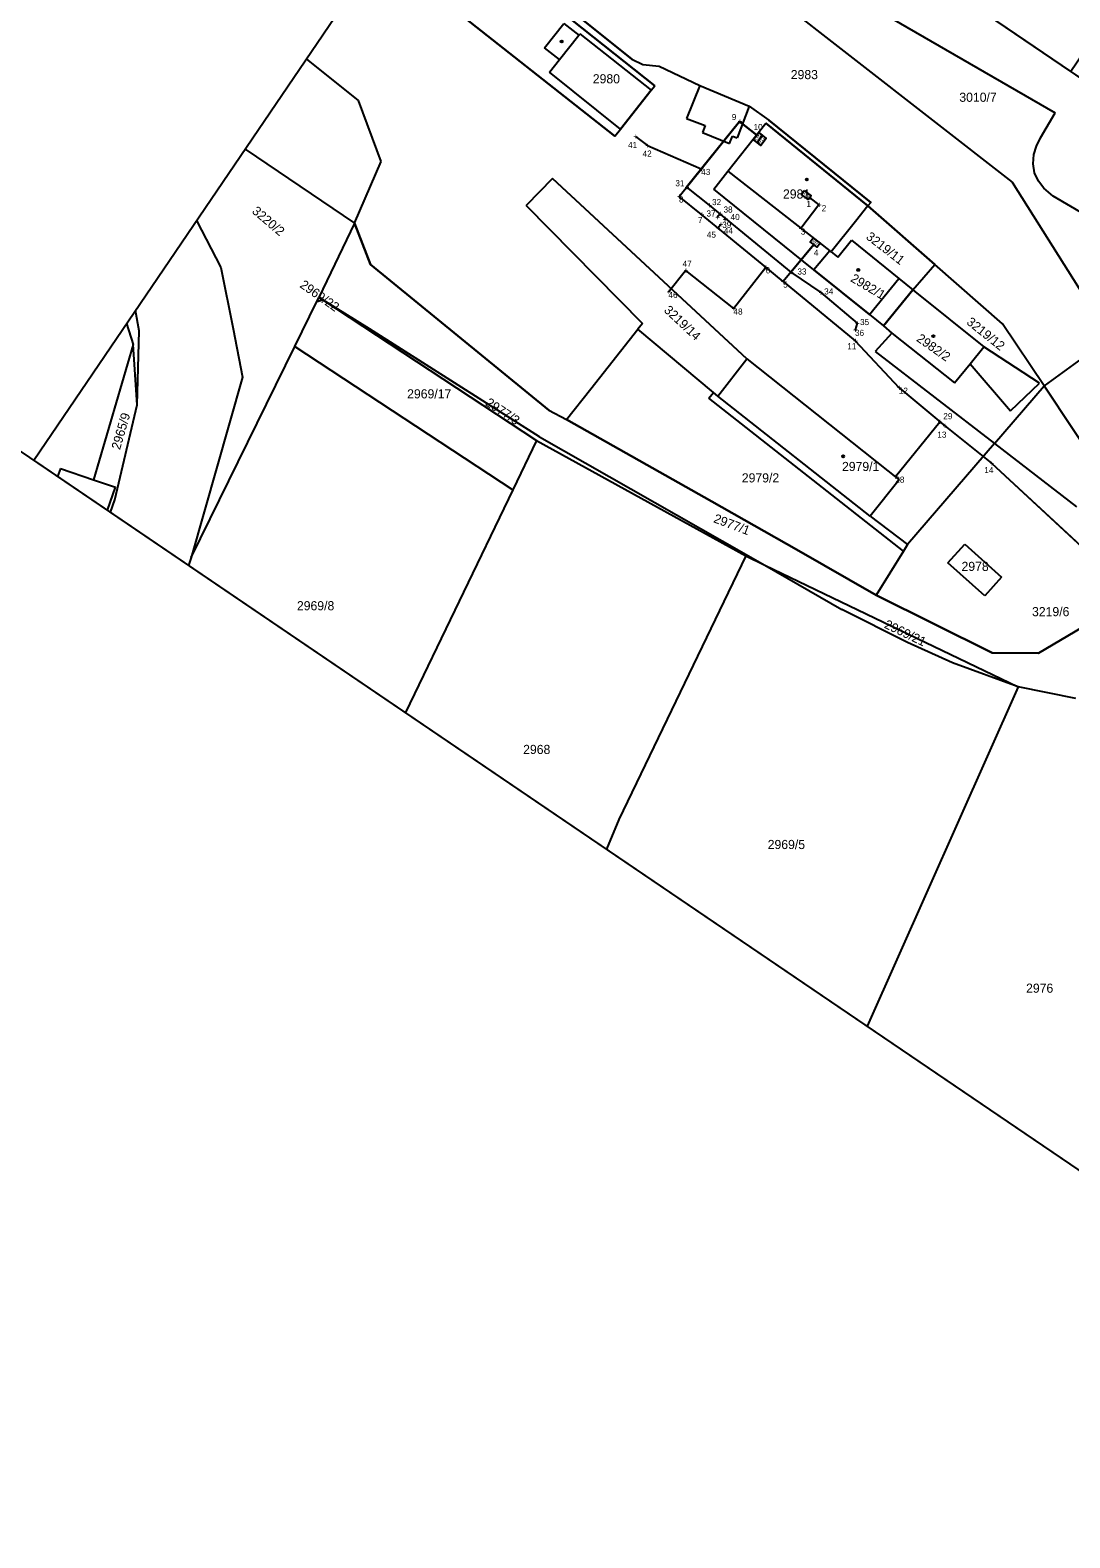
# Model space of a CAD drawing. Extents: x -620450 to -619936, y -1122925 to -1122443.
# Drawn here: x -620363.8 to -620193.1, y -1122924.7 to -1122677.1 of the extents above; entities that cross this region are included whole.
import ezdxf

# ---------------------------------------------------------------- set-up
doc = ezdxf.new("R2010")
doc.units = 0
for name, color, linetype in [('060603_ROZVODY_NN', 7, 'Continuous'), ('BODY', 7, 'Continuous'), ('BODY POPIS', 7, 'Continuous'), ('RÁMY', 7, 'Continuous'), ('UZEMNĚNÍ', 7, 'Continuous'), ('Vrstva 53', 7, 'Continuous'), ('Vrstva 55', 7, 'Continuous'), ('Vrstva 56', 7, 'Continuous'), ('Vrstva 57', 7, 'Continuous')]:
    doc.layers.add(name, color=color, linetype=linetype)

msp = doc.modelspace()

# ---------------------------------------------------------------- linework, layer by layer
at = {"layer": '060603_ROZVODY_NN'}
msp.add_line((-620250.43, -1122708.95), (-620250.9, -1122709.52), dxfattribs=at)
for points in [[(-620235.16, -1122712.24), (-620240.17, -1122718.34), (-620243.03, -1122716), (-620253.57, -1122707.33), (-620257.27, -1122704.36), (-620247.33, -1122692.03), (-620244.52, -1122694.3)], [(-620235.81, -1122704.58), (-620234.3, -1122705.74), (-620237.27, -1122709.63)], [(-620259, -1122720.03), (-620256.2, -1122716.51), (-620248.32, -1122722.77), (-620243.03, -1122716)], [(-620240.17, -1122718.34), (-620228.34, -1122728.07), (-620221.17, -1122735.76), (-620213.63, -1122742.04), (-620205.95, -1122748.19), (-620177.51, -1122774.52), (-620185.52, -1122781.05), (-620181.59, -1122785.57), (-620173.13, -1122796.4), (-620158.91, -1122820.61), (-620151.64, -1122838.53), (-620148.85, -1122845.74), (-620146.97, -1122851.79), (-620142.65, -1122873.56), (-620132.31, -1122871.72), (-620130.54, -1122883.68), (-620130.19, -1122888.41), (-620130.04, -1122888.39)]]:
    msp.add_lwpolyline(points, dxfattribs=at)
for points in [[(-620245.07, -1122694.99), (-620244.18, -1122693.87), (-620243.57, -1122694.36), (-620244.45, -1122695.48)], [(-620244.45, -1122695.48), (-620243.57, -1122694.36), (-620242.95, -1122694.85), (-620243.84, -1122695.97)], [(-620236.71, -1122703.4), (-620235.57, -1122704.27), (-620236.05, -1122704.89), (-620237.18, -1122704.03)], [(-620235.25, -1122711.18), (-620234.12, -1122712.05), (-620234.59, -1122712.68), (-620235.73, -1122711.81)]]:
    msp.add_lwpolyline(points, close=True, dxfattribs=at)
at = {"layer": 'RÁMY'}
for points in [[(-620196.37, -1122501.99), (-620109.51, -1122560.98), (-620192.94, -1122683.83), (-620279.8, -1122624.84)], [(-620366.66, -1122565.85), (-620019.21, -1122801.81), (-620102.64, -1122924.66), (-620450.09, -1122688.7)], [(-620279.8, -1122624.84), (-620019.21, -1122801.81), (-620102.64, -1122924.66), (-620363.23, -1122747.69)]]:
    msp.add_lwpolyline(points, close=True, dxfattribs=at)
at = {"layer": 'UZEMNĚNÍ'}
for p, q in [((-620250.99, -1122707.76), (-620250.55, -1122707.22)), ((-620249.79, -1122708.16), (-620249.64, -1122707.97))]:
    msp.add_line(p, q, dxfattribs=at)
for points in [[(-620244.52, -1122694.3), (-620247.33, -1122692.03), (-620256.03, -1122702.83), (-620252.31, -1122705.78), (-620238.9, -1122716.8), (-620235.16, -1122712.24)], [(-620264.43, -1122694.51), (-620262.46, -1122696.02), (-620253.62, -1122699.84)], [(-620238.9, -1122716.8), (-620233.99, -1122720.16), (-620228.02, -1122725.18), (-620228.37, -1122726.26)], [(-620221.75, -1122750.37), (-620214.46, -1122741.38), (-620205.95, -1122748.19), (-620176.84, -1122775.14)]]:
    msp.add_lwpolyline(points, dxfattribs=at)
at = {"layer": 'Vrstva 53'}
for p, q in [((-620299.15, -1122656.1), (-620261.22, -1122686.17)), ((-620298.73, -1122654.76), (-620265, -1122681.82)), ((-620267.81, -1122694.49), (-620302.66, -1122666.96)), ((-620309.9, -1122688.62), (-620318.44, -1122681.74)), ((-620265, -1122681.82), (-620263.22, -1122682.69)), ((-620263.22, -1122682.69), (-620260.55, -1122682.94)), ((-620260.55, -1122682.94), (-620253.83, -1122686.12)), ((-620261.82, -1122686.93), (-620261.22, -1122686.17)), ((-620253.83, -1122686.12), (-620245.73, -1122689.53)), ((-620306.2, -1122698.65), (-620309.9, -1122688.62)), ((-620261.82, -1122686.93), (-620266.86, -1122693.31)), ((-620245.73, -1122689.53), (-620242.51, -1122691.82)), ((-620267.81, -1122694.49), (-620266.86, -1122693.31)), ((-620249.26, -1122700.23), (-620243.01, -1122692.32)), ((-620226.24, -1122705.93), (-620243.01, -1122692.32)), ((-620310.57, -1122708.76), (-620306.2, -1122698.65)), ((-620251.53, -1122703.16), (-620249.26, -1122700.23)), ((-620278.07, -1122701.42), (-620282.38, -1122705.84)), ((-620278.07, -1122701.42), (-620246.12, -1122731.05)), ((-620235.14, -1122716.41), (-620251.53, -1122703.16)), ((-620263.28, -1122725.23), (-620282.38, -1122705.84)), ((-620226.24, -1122705.93), (-620228.28, -1122708.48)), ((-620226.24, -1122705.93), (-620215.29, -1122715.52)), ((-620228.28, -1122708.48), (-620232.27, -1122713.47)), ((-620307.94, -1122715.53), (-620310.57, -1122708.76)), ((-620232.51, -1122713.28), (-620235.14, -1122716.41)), ((-620232.27, -1122713.47), (-620232.51, -1122713.28)), ((-620232.27, -1122713.47), (-620231.2, -1122714.35)), ((-620231.2, -1122714.35), (-620228.95, -1122711.56)), ((-620228.95, -1122711.56), (-620221.19, -1122717.82)), ((-620278.65, -1122739.48), (-620307.94, -1122715.53)), ((-620218.86, -1122719.7), (-620215.29, -1122715.52)), ((-620226.02, -1122723.74), (-620235.14, -1122716.41)), ((-620221.19, -1122717.82), (-620218.86, -1122719.7)), ((-620218.86, -1122719.7), (-620223.68, -1122725.62)), ((-620263.28, -1122725.23), (-620264.06, -1122726.18)), ((-620226.02, -1122723.74), (-620223.68, -1122725.62)), ((-620223.68, -1122725.62), (-620222.3, -1122726.83)), ((-620271.78, -1122735.94), (-620264.06, -1122726.18)), ((-620251.62, -1122736.54), (-620264.06, -1122726.18)), ((-620222.3, -1122726.83), (-620225.04, -1122729.85)), ((-620225.04, -1122729.85), (-620205.48, -1122744.93)), ((-620250.89, -1122737.15), (-620246.12, -1122731.05)), ((-620246.12, -1122731.05), (-620221.1, -1122750.9)), ((-620205.48, -1122744.93), (-620197.33, -1122735.44)), ((-620197.33, -1122735.44), (-620187.9, -1122749.66)), ((-620275.74, -1122741.01), (-620271.78, -1122735.94)), ((-620252.35, -1122737.47), (-620251.62, -1122736.54)), ((-620220.43, -1122762.64), (-620252.35, -1122737.47)), ((-620250.89, -1122737.15), (-620251.62, -1122736.54)), ((-620278.65, -1122739.48), (-620275.74, -1122741.01)), ((-620251.9, -1122754.44), (-620275.74, -1122741.01)), ((-620205.48, -1122744.93), (-620219.74, -1122761.53)), ((-620221.1, -1122750.9), (-620225.88, -1122756.88)), ((-620238, -1122762.33), (-620251.9, -1122754.44)), ((-620225.88, -1122756.88), (-620219.74, -1122761.53)), ((-620224.92, -1122769.84), (-620238, -1122762.33)), ((-620220.43, -1122762.64), (-620224.92, -1122769.84)), ((-620219.74, -1122761.53), (-620220.43, -1122762.64)), ((-620213.13, -1122764.54), (-620210.34, -1122761.46)), ((-620210.34, -1122761.46), (-620204.3, -1122766.9)), ((-620207.05, -1122769.98), (-620213.13, -1122764.54)), ((-620204.3, -1122766.9), (-620207.05, -1122769.98)), ((-620205.84, -1122779.33), (-620224.92, -1122769.84)), ((-620191.03, -1122775.11), (-620198.25, -1122779.35)), ((-620198.25, -1122779.35), (-620205.84, -1122779.33))]:
    msp.add_line(p, q, dxfattribs=at)
msp.add_lwpolyline([(-620242.51, -1122691.82), (-620225.75, -1122705.35), (-620226.24, -1122705.93)], dxfattribs=at)
at = {"layer": 'Vrstva 55'}
for p, q in [((-620271, -1122646.92), (-620195.53, -1122690.65)), ((-620261.22, -1122686.17), (-620299.15, -1122656.1)), ((-620265, -1122681.82), (-620298.73, -1122654.76)), ((-620302.66, -1122666.96), (-620267.81, -1122694.49)), ((-620243.36, -1122670.23), (-620202.54, -1122702)), ((-620309.9, -1122688.62), (-620318.44, -1122681.74)), ((-620265, -1122681.82), (-620263.22, -1122682.69)), ((-620263.22, -1122682.69), (-620260.55, -1122682.94)), ((-620260.55, -1122682.94), (-620253.83, -1122686.12)), ((-620261.82, -1122686.93), (-620261.22, -1122686.17)), ((-620253.83, -1122686.12), (-620245.73, -1122689.53)), ((-620306.2, -1122698.65), (-620309.9, -1122688.62)), ((-620266.86, -1122693.31), (-620261.82, -1122686.93)), ((-620245.73, -1122689.53), (-620242.51, -1122691.82)), ((-620197.92, -1122694.75), (-620195.53, -1122690.65)), ((-620267.81, -1122694.49), (-620266.86, -1122693.31)), ((-620249.26, -1122700.23), (-620243.01, -1122692.32)), ((-620243.01, -1122692.32), (-620226.24, -1122705.93)), ((-620225.75, -1122705.35), (-620242.51, -1122691.82)), ((-620199.01, -1122697.5), (-620198.58, -1122696.08)), ((-620198.58, -1122696.08), (-620197.92, -1122694.75)), ((-620328.53, -1122696.6), (-620310.57, -1122708.76)), ((-620310.57, -1122708.76), (-620306.2, -1122698.65)), ((-620199.13, -1122698.99), (-620199.01, -1122697.5)), ((-620251.53, -1122703.16), (-620249.26, -1122700.23)), ((-620198.88, -1122700.47), (-620199.13, -1122698.99)), ((-620198.25, -1122701.83), (-620198.88, -1122700.47)), ((-620278.07, -1122701.42), (-620282.38, -1122705.84)), ((-620246.12, -1122731.05), (-620278.07, -1122701.42)), ((-620235.14, -1122716.41), (-620251.53, -1122703.16)), ((-620202.54, -1122702), (-620186.47, -1122727.64)), ((-620197.37, -1122703.03), (-620198.25, -1122701.83)), ((-620195.84, -1122704.31), (-620197.37, -1122703.03)), ((-620282.38, -1122705.84), (-620263.28, -1122725.23)), ((-620226.24, -1122705.93), (-620228.28, -1122708.48)), ((-620225.75, -1122705.35), (-620226.24, -1122705.93)), ((-620215.29, -1122715.52), (-620226.24, -1122705.93)), ((-620190.67, -1122707.32), (-620195.84, -1122704.31)), ((-620336.5, -1122708.34), (-620332.51, -1122716.01)), ((-620228.28, -1122708.48), (-620232.27, -1122713.47)), ((-620310.57, -1122708.76), (-620316.42, -1122720.94)), ((-620310.57, -1122708.76), (-620307.94, -1122715.53)), ((-620232.51, -1122713.28), (-620235.14, -1122716.41)), ((-620232.27, -1122713.47), (-620232.51, -1122713.28)), ((-620232.27, -1122713.47), (-620231.2, -1122714.35)), ((-620231.2, -1122714.35), (-620228.95, -1122711.56)), ((-620228.95, -1122711.56), (-620221.19, -1122717.82)), ((-620332.51, -1122716.01), (-620330.51, -1122726.08)), ((-620307.94, -1122715.53), (-620278.65, -1122739.48)), ((-620218.86, -1122719.7), (-620215.29, -1122715.52)), ((-620204.16, -1122725.27), (-620215.29, -1122715.52)), ((-620235.14, -1122716.41), (-620226.02, -1122723.74)), ((-620221.19, -1122717.82), (-620218.86, -1122719.7)), ((-620316.74, -1122721.6), (-620316.42, -1122720.94)), ((-620316.42, -1122720.94), (-620315.79, -1122721.36)), ((-620223.68, -1122725.62), (-620218.86, -1122719.7)), ((-620218.86, -1122719.7), (-620218.55, -1122719.95)), ((-620218.55, -1122719.95), (-620207.24, -1122729.07)), ((-620345.94, -1122726.44), (-620346.54, -1122723.11)), ((-620320.37, -1122729), (-620316.74, -1122721.6)), ((-620316.74, -1122721.6), (-620315.79, -1122721.36)), ((-620308.1, -1122726.09), (-620315.79, -1122721.36)), ((-620315.79, -1122721.36), (-620280.66, -1122744.45)), ((-620347.98, -1122725.23), (-620346.9, -1122728.66)), ((-620263.28, -1122725.23), (-620264.06, -1122726.18)), ((-620226.02, -1122723.74), (-620223.68, -1122725.62)), ((-620223.68, -1122725.62), (-620222.3, -1122726.83)), ((-620197.33, -1122735.44), (-620204.16, -1122725.27)), ((-620346.26, -1122738.61), (-620345.94, -1122726.44)), ((-620330.51, -1122726.08), (-620328.93, -1122734.05)), ((-620280.18, -1122743.84), (-620308.1, -1122726.09)), ((-620271.78, -1122735.94), (-620264.06, -1122726.18)), ((-620251.62, -1122736.54), (-620264.06, -1122726.18)), ((-620222.3, -1122726.83), (-620225.04, -1122729.85)), ((-620222.3, -1122726.83), (-620212.02, -1122735)), ((-620346.9, -1122728.66), (-620353.41, -1122750.9)), ((-620346.26, -1122738.61), (-620346.9, -1122728.66)), ((-620337.36, -1122763.66), (-620320.37, -1122729)), ((-620320.37, -1122729), (-620284.57, -1122752.56)), ((-620225.04, -1122729.85), (-620205.48, -1122744.93)), ((-620198.09, -1122735.05), (-620207.24, -1122729.07)), ((-620250.89, -1122737.15), (-620246.12, -1122731.05)), ((-620246.12, -1122731.05), (-620221.1, -1122750.9)), ((-620212.02, -1122735), (-620209.48, -1122731.85)), ((-620209.48, -1122731.85), (-620202.82, -1122739.59)), ((-620191.31, -1122731.11), (-620197.33, -1122735.44)), ((-620328.93, -1122734.05), (-620337.36, -1122763.66)), ((-620205.48, -1122744.93), (-620197.33, -1122735.44)), ((-620202.82, -1122739.59), (-620198.09, -1122735.05)), ((-620187.9, -1122749.66), (-620197.33, -1122735.44)), ((-620275.74, -1122741.01), (-620271.78, -1122735.94)), ((-620252.35, -1122737.47), (-620251.62, -1122736.54)), ((-620220.43, -1122762.64), (-620252.35, -1122737.47)), ((-620250.89, -1122737.15), (-620251.62, -1122736.54)), ((-620349.91, -1122754.18), (-620346.26, -1122738.61)), ((-620278.65, -1122739.48), (-620275.74, -1122741.01)), ((-620275.74, -1122741.01), (-620251.9, -1122754.44)), ((-620280.66, -1122744.45), (-620284.57, -1122752.56)), ((-620280.66, -1122744.45), (-620246.32, -1122763.41)), ((-620280.18, -1122743.84), (-620246.23, -1122763.17)), ((-620205.48, -1122744.93), (-620219.74, -1122761.53)), ((-620358.86, -1122749.03), (-620359.31, -1122750.35)), ((-620358.86, -1122749.03), (-620353.41, -1122750.9)), ((-620353.41, -1122750.9), (-620349.8, -1122752.13)), ((-620351.12, -1122755.91), (-620349.8, -1122752.13)), ((-620284.57, -1122752.56), (-620302.21, -1122789.13)), ((-620221.1, -1122750.9), (-620225.88, -1122756.88)), ((-620350.63, -1122756.24), (-620349.91, -1122754.18)), ((-620251.9, -1122754.44), (-620238, -1122762.33)), ((-620225.88, -1122756.88), (-620219.74, -1122761.53)), ((-620238, -1122762.33), (-620224.92, -1122769.84)), ((-620220.43, -1122762.64), (-620224.92, -1122769.84)), ((-620219.74, -1122761.53), (-620220.43, -1122762.64)), ((-620213.13, -1122764.54), (-620210.34, -1122761.46)), ((-620210.34, -1122761.46), (-620204.3, -1122766.9)), ((-620337.36, -1122763.66), (-620337.81, -1122764.95)), ((-620246.32, -1122763.41), (-620267.15, -1122806.71)), ((-620246.32, -1122763.41), (-620243.2, -1122764.91)), ((-620246.23, -1122763.17), (-620243.2, -1122764.91)), ((-620243.2, -1122764.91), (-620230.53, -1122772.18)), ((-620243.2, -1122764.91), (-620201.6, -1122784.9)), ((-620207.05, -1122769.98), (-620213.13, -1122764.54)), ((-620204.3, -1122766.9), (-620207.05, -1122769.98)), ((-620224.92, -1122769.84), (-620205.84, -1122779.33)), ((-620219.74, -1122777.62), (-620230.53, -1122772.18)), ((-620198.25, -1122779.35), (-620191.03, -1122775.11)), ((-620212.35, -1122780.98), (-620219.74, -1122777.62)), ((-620205.84, -1122779.33), (-620198.25, -1122779.35)), ((-620201.6, -1122784.9), (-620212.35, -1122780.98)), ((-620201.6, -1122784.9), (-620226.38, -1122840.63)), ((-620192.09, -1122786.79), (-620201.6, -1122784.9)), ((-620267.15, -1122806.71), (-620269.18, -1122811.56))]:
    msp.add_line(p, q, dxfattribs=at)
at = {"layer": 'Vrstva 56'}
for p, q in [((-620279.35, -1122679.94), (-620276.17, -1122675.94)), ((-620276.17, -1122675.94), (-620273.73, -1122677.87)), ((-620276.91, -1122681.88), (-620273.73, -1122677.87)), ((-620273.73, -1122677.87), (-620273.55, -1122677.64)), ((-620273.55, -1122677.64), (-620261.82, -1122686.93)), ((-620276.91, -1122681.88), (-620279.35, -1122679.94)), ((-620278.56, -1122683.97), (-620276.91, -1122681.88)), ((-620266.86, -1122693.31), (-620278.56, -1122683.97)), ((-620253.83, -1122686.12), (-620256.06, -1122691.57)), ((-620245.73, -1122689.53), (-620247.73, -1122694.76)), ((-620256.06, -1122691.57), (-620252.97, -1122692.73)), ((-620252.97, -1122692.73), (-620253.4, -1122693.88)), ((-620253.4, -1122693.88), (-620248.99, -1122695.65)), ((-620248.99, -1122695.65), (-620248.5, -1122694.45)), ((-620248.5, -1122694.45), (-620247.73, -1122694.76)), ((-620249.26, -1122700.23), (-620232.51, -1122713.28)), ((-620226.02, -1122723.74), (-620221.19, -1122717.82)), ((-620209.48, -1122731.85), (-620207.24, -1122729.07)), ((-620225.88, -1122756.88), (-620250.89, -1122737.15)), ((-620205.48, -1122744.93), (-620191.99, -1122755.33))]:
    msp.add_line(p, q, dxfattribs=at)
at = {"layer": 'Vrstva 57'}
for centre in [(-620276.54, -1122678.91), (-620236.29, -1122701.58), (-620227.84, -1122716.43), (-620215.5, -1122727.32), (-620230.31, -1122747.04)]:
    msp.add_circle(centre, 0.175, dxfattribs=at)

# ---------------------------------------------------------------- texts
at = {"layer": '060603_ROZVODY_NN'}
for s, rotation, p in [('KS5', 51.5727, (-620244.59, -1122695.35)), ('R11', 51.5727, (-620243.94, -1122695.78)), ('RV5', 322.5799, (-620237.07, -1122703.88)), ('RH', 322.5799, (-620235.47, -1122711.77))]:
    msp.add_text(s, height=0.5, rotation=rotation, dxfattribs=at).set_placement(p)
at = {"layer": 'BODY'}
for p in [(-620247.66, -1122692.53), (-620264.76, -1122695.01), (-620262.79, -1122696.52), (-620244.85, -1122694.8), (-620253.96, -1122700.34), (-620256.37, -1122703.33), (-620257.6, -1122704.86), (-620252.64, -1122706.28), (-620236.15, -1122705.08), (-620234.63, -1122706.24), (-620253.9, -1122707.83), (-620251.33, -1122708.26), (-620250.88, -1122707.72), (-620250.13, -1122708.66), (-620249.97, -1122708.47), (-620251.24, -1122710.02), (-620250.76, -1122709.45), (-620237.61, -1122710.13), (-620235.49, -1122712.74), (-620243.36, -1122716.5), (-620256.53, -1122717.01), (-620240.51, -1122718.84), (-620239.24, -1122717.3), (-620259.33, -1122720.53), (-620234.33, -1122720.66), (-620248.65, -1122723.27), (-620228.36, -1122725.68), (-620228.7, -1122726.76), (-620228.67, -1122728.57), (-620221.5, -1122736.26), (-620214.79, -1122741.88), (-620213.97, -1122742.54), (-620206.29, -1122748.69), (-620222.08, -1122750.87)]:
    msp.add_text('+', height=1, dxfattribs=at).set_placement(p)
at = {"layer": 'BODY POPIS'}
for s, p in [('9', (-620248.61, -1122691.82)), ('10', (-620245.03, -1122693.46)), ('41', (-620265.63, -1122696.4)), ('42', (-620263.25, -1122697.82)), ('43', (-620253.62, -1122700.84)), ('31', (-620257.87, -1122702.69)), ('8', (-620257.27, -1122705.36)), ('32', (-620251.85, -1122705.79)), ('38', (-620249.96, -1122707.01)), ('1', (-620236.35, -1122706.1)), ('2', (-620233.84, -1122706.79)), ('7', (-620254.16, -1122708.74)), ('37', (-620252.76, -1122707.66)), ('39', (-620250.18, -1122709.52)), ('40', (-620248.8, -1122708.23)), ('45', (-620252.7, -1122711.13)), ('44', (-620249.91, -1122710.5)), ('3', (-620237.27, -1122710.63)), ('4', (-620235.12, -1122714.08)), ('47', (-620256.68, -1122715.9)), ('6', (-620243.03, -1122717)), ('5', (-620240.17, -1122719.34)), ('33', (-620237.83, -1122717.19)), ('46', (-620259, -1122721.03)), ('34', (-620233.43, -1122720.46)), ('48', (-620248.32, -1122723.77)), ('35', (-620227.54, -1122725.49)), ('36', (-620228.37, -1122727.26)), ('11', (-620229.63, -1122729.45)), ('12', (-620221.17, -1122736.76)), ('29', (-620213.87, -1122740.95)), ('13', (-620214.85, -1122743.98)), ('28', (-620221.75, -1122751.37)), ('14', (-620207.13, -1122749.8))]:
    msp.add_text(s, height=1, dxfattribs=at).set_placement(p)
at = {"layer": 'Vrstva 57'}
for s, p in [('2983', (-620238.92, -1122685.1)), ('2980', (-620271.43, -1122685.79)), ('3010/7', (-620211.24, -1122688.82)), ('2981', (-620240.2, -1122704.71)), ('2969/17', (-620301.92, -1122737.53)), ('2979/1', (-620230.51, -1122749.46)), ('2979/2', (-620246.96, -1122751.33)), ('2978', (-620210.88, -1122765.87)), ('2969/8', (-620320.02, -1122772.33)), ('3219/6', (-620199.3, -1122773.3)), ('2968', (-620282.87, -1122795.93)), ('2969/5', (-620242.71, -1122811.54)), ('2976', (-620200.28, -1122835.14))]:
    msp.add_text(s, height=1.5, dxfattribs=at).set_placement(p)
for s, rotation, p in [('3220/2', 319.5, (-620327.51, -1122706.97)), ('3219/11', 322.1138, (-620226.69, -1122711.22)), ('2969/22', 324.8459, (-620319.67, -1122719.19)), ('2982/1', 329.4, (-620229.23, -1122718.23)), ('3219/14', 316.8, (-620259.86, -1122723.19)), ('3219/12', 321.2409, (-620210.18, -1122725.22)), ('2982/2', 324.9, (-620218.4, -1122728.01)), ('2977/3', 326.397, (-620289.18, -1122738.58)), ('2965/9', 73.8221, (-620349.08, -1122746.06)), ('2977/1', 339.3, (-620251.72, -1122757.84)), ('2969/21', 334.3112, (-620223.7, -1122775.15))]:
    msp.add_text(s, height=1.5, rotation=rotation, dxfattribs=at).set_placement(p)

doc.saveas('drawing.dxf')
